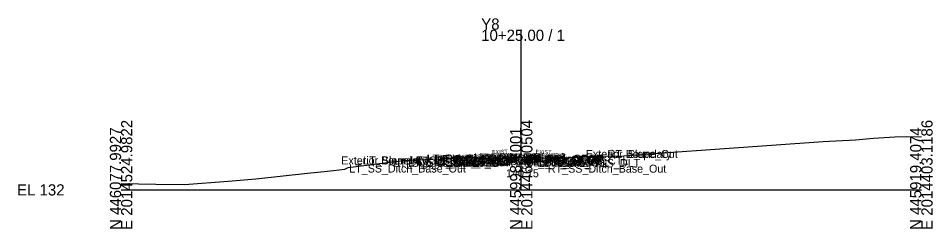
# Model space of a CAD drawing. Extents: x -26 to 1403, y -10 to 8043.
# Drawn here: x -25.7 to 202.8, y 490.3 to 542.8 of the extents above; entities that cross this region are included whole.
import ezdxf

# ---------------------------------------------------------------- set-up
doc = ezdxf.new("R2010")
doc.units = 0
for name, color, linetype in [('Default', 7, 'Continuous'), ('Exist Cross Section Cell', 7, 'Continuous'), ('Exist XS Center Line Elevation Label', 7, 'Continuous'), ('Exist XS Ground Line', 7, 'Continuous'), ('Prop CMT Pvmt Surface Shoulder', 7, 'Continuous'), ('Prop CMT Shld Paved Course 1', 7, 'Continuous'), ('Prop XS SE Text', 7, 'Continuous'), ('Scratch_Level_0', 7, 'Continuous')]:
    doc.layers.add(name, color=color, linetype=linetype)

msp = doc.modelspace()

# ---------------------------------------------------------------- linework, layer by layer
at = {"layer": 'Exist Cross Section Cell'}
for p, q in [((100, 500), (100, 540.01)), ((0, 500), (100, 500)), ((100, 500), (200, 500))]:
    msp.add_line(p, q, dxfattribs=at)
at = {"layer": 'Exist XS Ground Line'}
msp.add_lwpolyline([(0, 501.6), (8.67, 501.41), (15.84, 501.31), (26.72, 502.17), (33.66, 502.75), (46.58, 504.15), (50.75, 504.57), (52.29, 504.76), (53.09, 504.87), (55.9, 505.17), (56.77, 505.62), (70.52, 507.35), (83.4, 507.89), (88.82, 508.1), (88.94, 507.83), (95.07, 508), (100.24, 508.16), (105.26, 508.01), (110.64, 507.79), (113.27, 508.25), (119.03, 508.46), (125.65, 508.47), (131.11, 508.95), (132.43, 508.99), (136.74, 509.37), (148.46, 510.2), (175.46, 512.09), (183.55, 512.52), (188.07, 512.93), (193.35, 513.25), (196.34, 513.34), (200, 513.28)], dxfattribs=at)
at = {"layer": 'Prop CMT Pvmt Surface Shoulder'}
msp.add_lwpolyline([(110.64, 507.78), (110.64, 507.78)], dxfattribs=at)
at = {"layer": 'Prop CMT Shld Paved Course 1'}
for points in [[(88.94, 507.82), (88.94, 507.82)], [(110.64, 507.78), (110.64, 507.78)]]:
    msp.add_lwpolyline(points, dxfattribs=at)

# ---------------------------------------------------------------- texts
at = {"layer": 'Default'}
msp.add_text('-', height=0.0001, dxfattribs=at).set_placement((0, 500))
at = {"layer": 'Exist Cross Section Cell'}
for s, p in [('Y8', (90, 540.01)), ('10+25.00 / 1', (90, 537.21)), ('EL 132', (-26, 498.6))]:
    msp.add_text(s, height=2.8, dxfattribs=at).set_placement(p)
for s, p in [('E 2014524.9822', (2.8, 490)), ('E 2014464.0504', (102.8, 490)), ('E 2014403.1186', (202.8, 490)), ('N 446077.9927', (0, 490)), ('N 445998.7001', (100, 490)), ('N 445919.4074', (200, 490))]:
    msp.add_text(s, height=2.8, rotation=90, dxfattribs=at).set_placement(p)
at = {"layer": 'Exist XS Center Line Elevation Label'}
msp.add_text('140.15', height=2, dxfattribs=at).set_placement((96.22, 503.15))
at = {"layer": 'Prop XS SE Text'}
for rotation, p in [(1.7184, (92.67, 508.93)), (357.9955, (103.58, 509.02))]:
    msp.add_text('EXIST.', height=1, rotation=rotation, dxfattribs=at).set_placement(p)
at = {"layer": 'Scratch_Level_0'}
for s, p in [('Exterior Boundary', (116.14, 507.97)), ('RT_Slope_Cut', (121.59, 507.97)), ('Exterior Boundary', (55.03, 506.36)), ('LT_Slope_Cut', (60.53, 506.36)), ('LT_Sub_OSS_DLT', (68.11, 505.78)), ('LT_Sub_Trench_Out', (71.76, 505.91)), ('LT_GS_OS_CTL', (72.31, 506.34)), ('LT_PS3_Shelf_Out', (73.92, 506.3)), ('LT_Sub Tie Out', (76.28, 506.83)), ('LT_PV_OEEOP_EG', (76.49, 506.83)), ('LT_Sub_OEEOP', (78.16, 505.94)), ('LT_PV2_OEEOP', (78.25, 506.57)), ('LT_PV3_OEEOP', (78.25, 506.32)), ('LT_PS3_OEOP', (78.67, 506.31)), ('LT_PV1_OEEOP', (78.82, 506.69)), ('LT_PS2_OEOP', (78.92, 506.56)), ('LT_Sub_OEOT', (79.02, 505.94)), ('LT_PV2_OEOT', (79.12, 506.57)), ('LT_PV3_OEOT', (79.12, 506.32)), ('LT_PV1_OEOT', (79.68, 506.82)), ('LT_PS1_OEOP', (79.75, 506.82)), ('LT_PV_IEEOP_EG', (88.19, 507.15)), ('RT_Sub_OEEOP', (89.17, 506.27)), ('RT_PV2_OEEOP', (89.26, 506.9)), ('RT_PV3_OEEOP', (89.26, 506.65)), ('RT_PV1_OEEOP', (89.83, 507.02)), ('RT_PV2_IEEOP', (89.91, 506.9)), ('LT_PV2_IEEOP', (89.95, 506.9)), ('LT_PV3_IEEOP', (89.95, 506.65)), ('RT_PV1_IEEOP', (90.47, 507.02)), ('LT_PV1_IEEOP', (90.52, 507.02)), ('PV2_PGL', (93.91, 506.9)), ('PV1_PGL', (94.47, 507.15)), ('RT_Sub_Trench_Out', (96.19, 505.87)), ('RT_PS3_Shelf_Out', (97.59, 506.26)), ('RT_Sub_OEOT', (100.67, 505.9)), ('RT_PV2_OEOT', (100.77, 506.53)), ('RT_PV3_OEOT', (100.77, 506.28)), ('RT_PS2_OEOP', (101.08, 506.52)), ('RT_PV1_OEOT', (101.33, 506.78)), ('RT_PS3_OEOP', (101.34, 506.27)), ('RT_PS1_OEOP', (101.4, 506.78)), ('RT_GS_OS_CTL', (105.96, 506.3)), ('RT_Sub_OSS_DLT', (106.23, 505.74)), ('LT_SS_Ditch_Base_Out', (57.02, 504.34)), ('RT_SS_Ditch_Base_Out', (106.67, 504.3))]:
    msp.add_text(s, height=2, dxfattribs=at).set_placement(p)

doc.saveas('drawing.dxf')
